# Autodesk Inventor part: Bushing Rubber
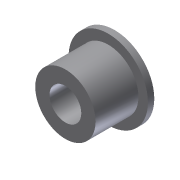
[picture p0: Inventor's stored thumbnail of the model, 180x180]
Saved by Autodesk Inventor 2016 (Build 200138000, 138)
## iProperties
Created: 2010-03
Part Number: Bushing Rubber
Document SubType Name: Modeling
Designer: bhakira
Density: 1 g/cm^3
Material: Generic
Appearance: Default
Author: bhakira
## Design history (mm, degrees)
sketch "Sketch1"
  geometry: L1 (25, 31)-(25, 27); L2 (25, 27)-(19, 27); L3 (19, 27)-(19, 0); L4 (19, 0)-(0, 0); L5 (0, 0)-(0, 31); L6 (0, 31)-(25, 31); 1 further point
  constraints: 12 end point, 1 coincident, 1 other
  dimensions: "d1" = 50 diameter of L1 L5; "d2" = 38 diameter of L3 L5; "d3" = 4 distance of L1.start L1.end; "d4" = 27 distance between parallel lines of L4 L2
revolve "Revolution1" sketch "Sketch1" stored, may be unused: angle "d5" = 90 deg
hole "Hole1" diameter "d8" = 20; stored, may be unused: countersink angle "d12" = 82 deg, drill point angle "d14" = 118 deg; dims "d6" = 10, "d7" = 10, "d9" = 6, "d10" = 34.925, "d11" = 2, "d13" = 8
body "Solid1"
